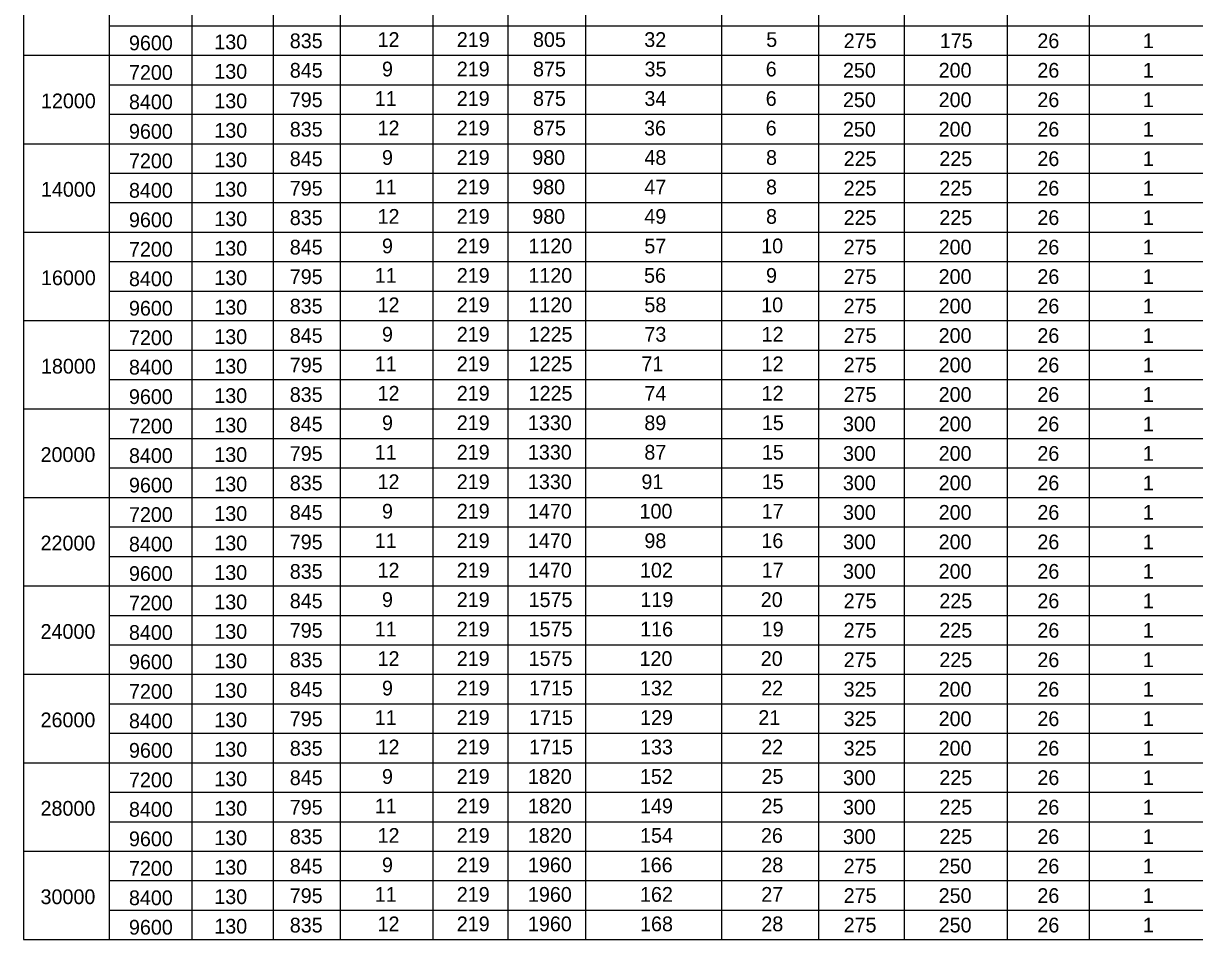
# Model space of a CAD drawing. Extents: x -5022 to -159, y 1126 to 7226.
# Drawn here: x -4608 to -4369.6, y 4908 to 5094.4 of the extents above; entities that cross this region are included whole.
import ezdxf

# ---------------------------------------------------------------- set-up
doc = ezdxf.new("R2010")
doc.units = 0
doc.layers.add('2', color=7, linetype='Continuous')
doc.layers.add('3', color=7, linetype='Continuous')

msp = doc.modelspace()

# ---------------------------------------------------------------- linework, layer by layer
at = {"layer": '3'}
for p, q in [((-4608.03, 5258.76), (-4608.03, 4907.95)), ((-4590.56, 5240.77), (-4590.56, 4907.95)), ((-4573.76, 5240.77), (-4573.76, 4907.95)), ((-4557.2, 5240.77), (-4557.2, 4907.95)), ((-4543.56, 5240.77), (-4543.56, 4907.95)), ((-4524.71, 5240.77), (-4524.71, 4907.95)), ((-4509.41, 5240.77), (-4509.41, 4907.95)), ((-4493.61, 5240.77), (-4493.61, 4907.95)), ((-4465.9, 5240.77), (-4465.9, 4907.95)), ((-4446.21, 5240.77), (-4446.21, 4907.95)), ((-4428.74, 5240.77), (-4428.74, 4907.95)), ((-4407.75, 5240.77), (-4407.75, 4907.95)), ((-4391.11, 5240.77), (-4391.11, 4907.95)), ((-4590.56, 5093.96), (-3894.3, 5093.96)), ((-4608.03, 5087.96), (-3894.3, 5087.96)), ((-4590.56, 5081.96), (-3894.3, 5081.96)), ((-4590.56, 5075.96), (-3894.3, 5075.96)), ((-4608.03, 5069.96), (-3894.3, 5069.96)), ((-4590.56, 5063.96), (-3894.3, 5063.96)), ((-4590.56, 5057.96), (-3894.3, 5057.96)), ((-4608.03, 5051.95), (-3894.3, 5051.96)), ((-4590.56, 5045.96), (-3894.3, 5045.96)), ((-4590.56, 5039.96), (-3894.3, 5039.96)), ((-4608.03, 5033.96), (-3894.3, 5033.96)), ((-4590.56, 5027.96), (-3894.3, 5027.96)), ((-4590.56, 5021.96), (-3894.3, 5021.96)), ((-4608.03, 5015.96), (-3894.3, 5015.96)), ((-4590.56, 5009.96), (-3894.3, 5009.96)), ((-4590.56, 5003.96), (-3894.3, 5003.96)), ((-4608.03, 4997.95), (-3894.3, 4997.96)), ((-4590.56, 4991.95), (-3894.3, 4991.96)), ((-4590.56, 4985.95), (-3894.3, 4985.96)), ((-4608.03, 4979.96), (-3894.3, 4979.96)), ((-4590.56, 4973.95), (-3894.3, 4973.96)), ((-4590.56, 4967.96), (-3894.3, 4967.96)), ((-4608.03, 4961.96), (-3894.3, 4961.96)), ((-4590.56, 4955.96), (-3894.3, 4955.96)), ((-4590.56, 4949.95), (-3894.3, 4949.96)), ((-4608.03, 4943.95), (-3894.3, 4943.95)), ((-4590.56, 4937.95), (-3894.3, 4937.95)), ((-4590.56, 4931.95), (-3894.3, 4931.96)), ((-4608.03, 4925.95), (-3894.3, 4925.95)), ((-4590.56, 4919.95), (-3894.3, 4919.96)), ((-4590.56, 4913.95), (-3894.3, 4913.96)), ((-4608.03, 4907.95), (-3894.3, 4907.96))]:
    msp.add_line(p, q, dxfattribs=at)

# ---------------------------------------------------------------- texts
at = {"layer": '2'}
for s, p in [('12', (-4535.94, 5089.66)), ('219', (-4519.81, 5089.66)), ('805', (-4504.3, 5089.66)), ('32', (-4481.64, 5089.66)), ('5', (-4456.82, 5089.66)), ('9600', (-4586.55, 5088.97)), ('130', (-4569.18, 5089.18)), ('835', (-4553.81, 5089.4)), ('275', (-4441.06, 5089.41)), ('175', (-4421.48, 5089.41)), ('26', (-4401.62, 5089.41)), ('1', (-4380.15, 5089.41)), ('7200', (-4586.55, 5082.97)), ('130', (-4569.18, 5083.18)), ('845', (-4553.81, 5083.4)), ('9', (-4535.04, 5083.66)), ('219', (-4519.81, 5083.66)), ('875', (-4504.3, 5083.66)), ('35', (-4481.58, 5083.66)), ('6', (-4456.92, 5083.66)), ('250', (-4441.2, 5083.41)), ('200', (-4421.71, 5083.41)), ('26', (-4401.62, 5083.41)), ('1', (-4380.15, 5083.41)), ('219', (-4519.81, 5077.66)), ('875', (-4504.3, 5077.66)), ('34', (-4481.61, 5077.66)), ('6', (-4456.92, 5077.66)), ('12000', (-4604.46, 5077.17)), ('8400', (-4586.55, 5076.97)), ('130', (-4569.18, 5077.18)), ('795', (-4553.81, 5077.4)), ('11', (-4536.51, 5077.66)), ('250', (-4441.2, 5077.41)), ('200', (-4421.71, 5077.41)), ('26', (-4401.62, 5077.41)), ('1', (-4380.15, 5077.41)), ('9600', (-4586.55, 5070.97)), ('130', (-4569.18, 5071.18)), ('835', (-4553.81, 5071.4)), ('12', (-4535.94, 5071.65)), ('219', (-4519.81, 5071.65)), ('875', (-4504.3, 5071.65)), ('36', (-4481.69, 5071.65)), ('6', (-4456.92, 5071.65)), ('250', (-4441.2, 5071.41)), ('200', (-4421.71, 5071.41)), ('26', (-4401.62, 5071.41)), ('1', (-4380.15, 5071.41)), ('7200', (-4586.55, 5064.97)), ('130', (-4569.18, 5065.18)), ('845', (-4553.81, 5065.39)), ('9', (-4535.04, 5065.65)), ('219', (-4519.81, 5065.65)), ('980', (-4504.45, 5065.65)), ('48', (-4481.62, 5065.65)), ('8', (-4456.86, 5065.65)), ('225', (-4441.06, 5065.41)), ('225', (-4421.57, 5065.41)), ('26', (-4401.62, 5065.41)), ('1', (-4380.15, 5065.41)), ('14000', (-4604.46, 5059.17)), ('8400', (-4586.55, 5058.97)), ('130', (-4569.18, 5059.18)), ('795', (-4553.81, 5059.39)), ('11', (-4536.51, 5059.65)), ('219', (-4519.81, 5059.65)), ('980', (-4504.45, 5059.65)), ('47', (-4481.63, 5059.65)), ('8', (-4456.86, 5059.65)), ('225', (-4441.06, 5059.41)), ('225', (-4421.57, 5059.41)), ('26', (-4401.62, 5059.41)), ('1', (-4380.15, 5059.41)), ('9600', (-4586.55, 5052.97)), ('130', (-4569.18, 5053.18)), ('835', (-4553.81, 5053.4)), ('12', (-4535.94, 5053.66)), ('219', (-4519.81, 5053.66)), ('980', (-4504.45, 5053.66)), ('49', (-4481.63, 5053.66)), ('8', (-4456.86, 5053.66)), ('225', (-4441.06, 5053.41)), ('225', (-4421.57, 5053.41)), ('26', (-4401.62, 5053.41)), ('1', (-4380.15, 5053.41)), ('7200', (-4586.55, 5046.97)), ('130', (-4569.18, 5047.18)), ('845', (-4553.81, 5047.4)), ('9', (-4535.04, 5047.65)), ('219', (-4519.81, 5047.65)), ('1120', (-4505.24, 5047.65)), ('57', (-4481.63, 5047.65)), ('10', (-4457.84, 5047.65)), ('275', (-4441.06, 5047.41)), ('200', (-4421.71, 5047.41)), ('26', (-4401.62, 5047.41)), ('1', (-4380.15, 5047.41)), ('16000', (-4604.46, 5041.17)), ('8400', (-4586.55, 5040.97)), ('130', (-4569.18, 5041.18)), ('795', (-4553.81, 5041.39)), ('11', (-4536.51, 5041.65)), ('219', (-4519.81, 5041.65)), ('1120', (-4505.24, 5041.65)), ('56', (-4481.69, 5041.65)), ('9', (-4456.86, 5041.65)), ('275', (-4441.06, 5041.41)), ('200', (-4421.71, 5041.41)), ('26', (-4401.62, 5041.41)), ('1', (-4380.15, 5041.41)), ('9600', (-4586.55, 5034.97)), ('130', (-4569.18, 5035.18)), ('835', (-4553.81, 5035.4)), ('12', (-4535.94, 5035.66)), ('219', (-4519.81, 5035.66)), ('1120', (-4505.24, 5035.66)), ('58', (-4481.62, 5035.66)), ('10', (-4457.84, 5035.66)), ('275', (-4441.06, 5035.41)), ('200', (-4421.71, 5035.41)), ('26', (-4401.62, 5035.41)), ('1', (-4380.15, 5035.41)), ('7200', (-4586.55, 5028.97)), ('130', (-4569.18, 5029.18)), ('845', (-4553.81, 5029.4)), ('9', (-4535.04, 5029.66)), ('219', (-4519.81, 5029.66)), ('1225', (-4505.19, 5029.66)), ('73', (-4481.62, 5029.66)), ('12', (-4457.76, 5029.66)), ('275', (-4441.06, 5029.41)), ('200', (-4421.71, 5029.41)), ('26', (-4401.62, 5029.41)), ('1', (-4380.15, 5029.41)), ('18000', (-4604.46, 5023.17)), ('8400', (-4586.55, 5022.97)), ('130', (-4569.18, 5023.18)), ('795', (-4553.81, 5023.4)), ('11', (-4536.51, 5023.65)), ('219', (-4519.81, 5023.65)), ('1225', (-4505.19, 5023.65)), ('71', (-4482.22, 5023.65)), ('12', (-4457.76, 5023.65)), ('275', (-4441.06, 5023.41)), ('200', (-4421.71, 5023.41)), ('26', (-4401.62, 5023.41)), ('1', (-4380.15, 5023.41)), ('9600', (-4586.55, 5016.97)), ('130', (-4569.18, 5017.18)), ('835', (-4553.81, 5017.39)), ('12', (-4535.94, 5017.65)), ('219', (-4519.81, 5017.65)), ('1225', (-4505.19, 5017.65)), ('74', (-4481.61, 5017.65)), ('12', (-4457.76, 5017.65)), ('275', (-4441.06, 5017.41)), ('200', (-4421.71, 5017.41)), ('26', (-4401.62, 5017.41)), ('1', (-4380.15, 5017.41)), ('7200', (-4586.55, 5010.97)), ('130', (-4569.18, 5011.18)), ('845', (-4553.81, 5011.39)), ('9', (-4535.04, 5011.65)), ('219', (-4519.81, 5011.65)), ('1330', (-4505.33, 5011.65)), ('89', (-4481.63, 5011.65)), ('15', (-4457.7, 5011.65)), ('300', (-4441.2, 5011.41)), ('200', (-4421.71, 5011.41)), ('26', (-4401.62, 5011.41)), ('1', (-4380.15, 5011.41)), ('20000', (-4604.55, 5005.17)), ('8400', (-4586.55, 5004.97)), ('130', (-4569.18, 5005.18)), ('795', (-4553.81, 5005.39)), ('11', (-4536.51, 5005.65)), ('219', (-4519.81, 5005.65)), ('1330', (-4505.33, 5005.65)), ('87', (-4481.63, 5005.65)), ('15', (-4457.7, 5005.65)), ('300', (-4441.2, 5005.41)), ('200', (-4421.71, 5005.41)), ('26', (-4401.62, 5005.41)), ('1', (-4380.15, 5005.41)), ('9600', (-4586.55, 4998.97)), ('130', (-4569.18, 4999.18)), ('835', (-4553.81, 4999.39)), ('12', (-4535.94, 4999.65)), ('219', (-4519.81, 4999.65)), ('1330', (-4505.33, 4999.65)), ('91', (-4482.22, 4999.65)), ('15', (-4457.7, 4999.65)), ('300', (-4441.2, 4999.41)), ('200', (-4421.71, 4999.41)), ('26', (-4401.62, 4999.41)), ('1', (-4380.15, 4999.41)), ('7200', (-4586.55, 4992.97)), ('130', (-4569.18, 4993.18)), ('845', (-4553.81, 4993.39)), ('9', (-4535.04, 4993.65)), ('219', (-4519.81, 4993.65)), ('1470', (-4505.33, 4993.65)), ('100', (-4482.61, 4993.65)), ('17', (-4457.74, 4993.65)), ('300', (-4441.2, 4993.41)), ('200', (-4421.71, 4993.41)), ('26', (-4401.62, 4993.41)), ('1', (-4380.15, 4993.41)), ('22000', (-4604.55, 4987.17)), ('130', (-4569.18, 4987.18)), ('795', (-4553.81, 4987.39)), ('11', (-4536.51, 4987.65)), ('219', (-4519.81, 4987.65)), ('1470', (-4505.33, 4987.65)), ('98', (-4481.62, 4987.65)), ('16', (-4457.8, 4987.65)), ('300', (-4441.2, 4987.41)), ('200', (-4421.71, 4987.41)), ('26', (-4401.62, 4987.41)), ('1', (-4380.15, 4987.41)), ('8400', (-4586.55, 4986.96)), ('9600', (-4586.55, 4980.96)), ('130', (-4569.18, 4981.18)), ('835', (-4553.81, 4981.39)), ('12', (-4535.94, 4981.65)), ('219', (-4519.81, 4981.65)), ('1470', (-4505.33, 4981.65)), ('102', (-4482.52, 4981.65)), ('17', (-4457.74, 4981.65)), ('300', (-4441.2, 4981.41)), ('200', (-4421.71, 4981.41)), ('26', (-4401.62, 4981.41)), ('1', (-4380.15, 4981.41)), ('130', (-4569.18, 4975.18)), ('845', (-4553.81, 4975.39)), ('9', (-4535.04, 4975.65)), ('219', (-4519.81, 4975.65)), ('1575', (-4505.19, 4975.65)), ('119', (-4482.42, 4975.65)), ('20', (-4457.93, 4975.65)), ('275', (-4441.06, 4975.41)), ('225', (-4421.57, 4975.41)), ('26', (-4401.62, 4975.41)), ('1', (-4380.15, 4975.41)), ('7200', (-4586.55, 4974.96)), ('24000', (-4604.55, 4969.17)), ('8400', (-4586.55, 4968.96)), ('130', (-4569.18, 4969.18)), ('795', (-4553.81, 4969.39)), ('11', (-4536.51, 4969.65)), ('219', (-4519.81, 4969.65)), ('1575', (-4505.19, 4969.65)), ('116', (-4482.48, 4969.65)), ('19', (-4457.74, 4969.65)), ('275', (-4441.06, 4969.41)), ('225', (-4421.57, 4969.41)), ('26', (-4401.62, 4969.41)), ('1', (-4380.15, 4969.41)), ('835', (-4553.81, 4963.39)), ('12', (-4535.94, 4963.65)), ('219', (-4519.81, 4963.65)), ('1575', (-4505.19, 4963.65)), ('120', (-4482.61, 4963.65)), ('20', (-4457.93, 4963.65)), ('275', (-4441.06, 4963.41)), ('225', (-4421.57, 4963.41)), ('26', (-4401.62, 4963.41)), ('1', (-4380.15, 4963.41)), ('9600', (-4586.55, 4962.97)), ('130', (-4569.18, 4963.18)), ('7200', (-4586.55, 4956.97)), ('130', (-4569.18, 4957.18)), ('845', (-4553.81, 4957.39)), ('9', (-4535.04, 4957.65)), ('219', (-4519.81, 4957.65)), ('1715', (-4505.1, 4957.65)), ('132', (-4482.52, 4957.65)), ('22', (-4457.84, 4957.65)), ('325', (-4441.06, 4957.41)), ('200', (-4421.71, 4957.41)), ('26', (-4401.62, 4957.41)), ('1', (-4380.15, 4957.41)), ('795', (-4553.81, 4951.39)), ('11', (-4536.51, 4951.65)), ('219', (-4519.81, 4951.65)), ('1715', (-4505.1, 4951.65)), ('129', (-4482.5, 4951.65)), ('21', (-4458.42, 4951.65)), ('325', (-4441.06, 4951.41)), ('200', (-4421.71, 4951.41)), ('26', (-4401.62, 4951.41)), ('1', (-4380.15, 4951.41)), ('26000', (-4604.55, 4951.17)), ('8400', (-4586.55, 4950.97)), ('130', (-4569.18, 4951.18)), ('9600', (-4586.55, 4944.97)), ('130', (-4569.18, 4945.18)), ('835', (-4553.81, 4945.39)), ('12', (-4535.94, 4945.65)), ('219', (-4519.81, 4945.65)), ('1715', (-4505.1, 4945.65)), ('133', (-4482.5, 4945.65)), ('22', (-4457.84, 4945.65)), ('325', (-4441.06, 4945.41)), ('200', (-4421.71, 4945.41)), ('26', (-4401.62, 4945.41)), ('1', (-4380.15, 4945.41)), ('845', (-4553.81, 4939.39)), ('9', (-4535.04, 4939.65)), ('219', (-4519.81, 4939.65)), ('1820', (-4505.33, 4939.65)), ('152', (-4482.52, 4939.65)), ('25', (-4457.78, 4939.65)), ('300', (-4441.2, 4939.41)), ('225', (-4421.57, 4939.41)), ('26', (-4401.62, 4939.41)), ('1', (-4380.15, 4939.41)), ('7200', (-4586.55, 4938.96)), ('130', (-4569.18, 4939.18)), ('28000', (-4604.55, 4933.17)), ('8400', (-4586.55, 4932.96)), ('130', (-4569.18, 4933.18)), ('795', (-4553.81, 4933.39)), ('11', (-4536.51, 4933.65)), ('219', (-4519.81, 4933.65)), ('1820', (-4505.33, 4933.65)), ('149', (-4482.5, 4933.65)), ('25', (-4457.78, 4933.65)), ('300', (-4441.2, 4933.41)), ('225', (-4421.57, 4933.41)), ('26', (-4401.62, 4933.41)), ('1', (-4380.15, 4933.41)), ('12', (-4535.94, 4927.65)), ('219', (-4519.81, 4927.65)), ('1820', (-4505.33, 4927.65)), ('154', (-4482.49, 4927.65)), ('26', (-4457.89, 4927.65)), ('9600', (-4586.55, 4926.96)), ('130', (-4569.18, 4927.18)), ('835', (-4553.81, 4927.39)), ('300', (-4441.2, 4927.41)), ('225', (-4421.57, 4927.41)), ('26', (-4401.62, 4927.41)), ('1', (-4380.15, 4927.41)), ('7200', (-4586.55, 4920.96)), ('130', (-4569.18, 4921.18)), ('845', (-4553.81, 4921.39)), ('9', (-4535.04, 4921.65)), ('219', (-4519.81, 4921.65)), ('1960', (-4505.33, 4921.65)), ('166', (-4482.56, 4921.65)), ('28', (-4457.82, 4921.65)), ('275', (-4441.06, 4921.41)), ('250', (-4421.71, 4921.41)), ('26', (-4401.62, 4921.41)), ('1', (-4380.15, 4921.41)), ('11', (-4536.51, 4915.65)), ('219', (-4519.81, 4915.65)), ('1960', (-4505.33, 4915.65)), ('162', (-4482.52, 4915.65)), ('27', (-4457.83, 4915.65)), ('30000', (-4604.55, 4915.17)), ('8400', (-4586.55, 4914.96)), ('130', (-4569.18, 4915.18)), ('795', (-4553.81, 4915.39)), ('275', (-4441.06, 4915.41)), ('250', (-4421.71, 4915.41)), ('26', (-4401.62, 4915.41)), ('1', (-4380.15, 4915.41)), ('9600', (-4586.55, 4908.96)), ('130', (-4569.18, 4909.18)), ('835', (-4553.81, 4909.39)), ('12', (-4535.94, 4909.65)), ('219', (-4519.81, 4909.65)), ('1960', (-4505.33, 4909.65)), ('168', (-4482.5, 4909.65)), ('28', (-4457.82, 4909.65)), ('275', (-4441.06, 4909.41)), ('250', (-4421.71, 4909.41)), ('26', (-4401.62, 4909.41)), ('1', (-4380.15, 4909.41))]:
    msp.add_text(s, height=3, dxfattribs=at).set_placement(p)

doc.saveas('drawing.dxf')
